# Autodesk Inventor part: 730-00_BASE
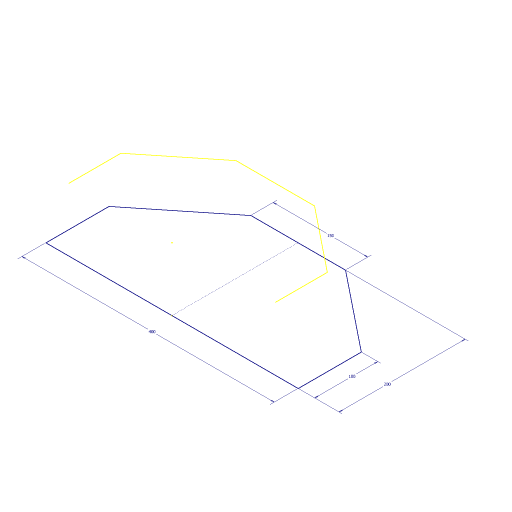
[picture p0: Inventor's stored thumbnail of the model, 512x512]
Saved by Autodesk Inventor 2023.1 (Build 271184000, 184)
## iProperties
Company: Fabian Stasiak CAD Consulting
Category: Autodesk® Inventor® Tutorial Series
Created: 2018-03
Part Number: 730-00_BASE
Material: Stal
Document SubType Name: Konstrukcja blachowa
Designer: F.Stasiak
Density: 7.85 g/cm^3
Sheet Metal Rule: Steel 2 mm
Appearance: Częściowo polerowany
Catalog Web Link: www.expertbooks.eu
FLATAREA: =<FLAT PATTERN AREA>
Thickness: 2
Author: F.Stasiak
Subject: Sheet Metal Design. Basic and Advanced techniques
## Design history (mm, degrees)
sketch "COVER SKETCH1"
  geometry: L1 (-200, 0)-(200, 0); L2 (200, 0)-(200, 100); L3 (200, 100)-(75, 200); L4 (75, 200)-(-75, 200); L5 (-75, 200)-(-200, 100); L6 (-200, 100)-(-200, 0); L7 (0, 0)-(0, 200); 1 further point
  constraints: 14 end point, 2 midpoint, 2 perpendicular, 1 coincident, 1 horizontal, 1 parallel, 1 vertical, 1 other
  dimensions: "d0" = 400 distance of L1.start L1.end; "d1" = 200 distance between parallel lines of L4 L1; "d2" = 100 distance of L1.end L2.end; "d3" = 150 distance of L3.end L4.end
feature "PowWyciągnięciaProstego1" dims "d4" = 100, "d5" = -20 deg
sketch "BASE SKETCH"
  geometry: L1 (-200, 100)-(-200, 0) reference; L2 (-75, 200)-(-200, 100) reference; L3 (75, 200)-(-75, 200) reference; L4 (200, 100)-(75, 200) reference; L5 (200, 0)-(200, 100) reference; L6 (-200, 0)-(200, 0); 1 further point
  constraints: 2 end point, 1 horizontal
node "Płaszczyzna konstrukcyjna1"
sketch "COVER SKETCH2"
  geometry: L1 (-163.603, 0)-(-163.603, 82.507) reference; L2 (-163.603, 82.507)-(-62.233, 163.603) reference; L3 (-62.233, 163.603)-(62.233, 163.603) reference; L4 (62.233, 163.603)-(163.603, 82.507) reference; L5 (163.603, 82.507)-(163.603, 0) reference; 1 further point
body "Solid3"
body "Srf1"
other parameters: "Thickness" = 2 (derived), "WspółczynnikK" = 4.4, "BendRadius" = 2 (= Thickness), "BendReliefWidth" = 2 (= Thickness), "BendReliefDepth" = 1 (= 0.5 x Thickness), "CornerReliefSize" = 8 (= 4 x Thickness), "OdstępPołączenia" = 0.01, "MinimumRemnant" = 4 (= 2 x Thickness), "TransitionRadius" = 2 (= BendRadius), "JacobiRadiusSize" = 2 (= BendRadius), "GapSize" = 2 (= Thickness), "d13" = 2 (= Thickness)
